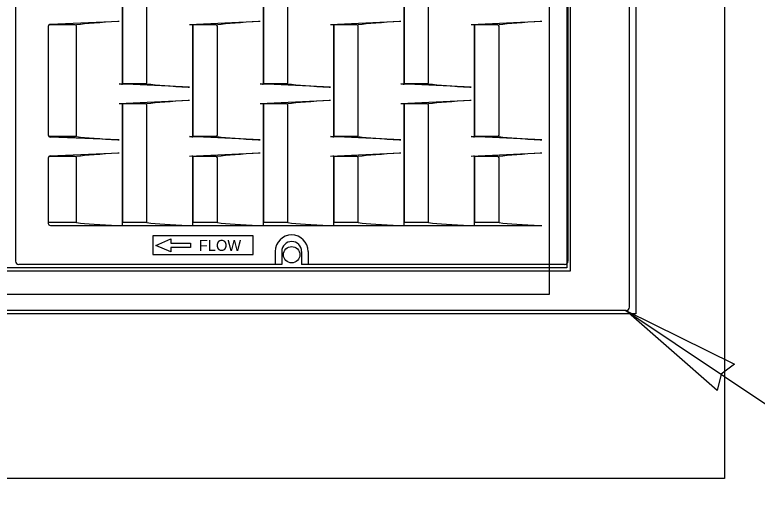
# Model space of a CAD drawing. Extents: x 99862 to 103151, y 100000 to 102076.
# Drawn here: x 101385.1 to 101526.3, y 101533.5 to 101624.9 of the extents above; entities that cross this region are included whole.
import ezdxf

# ---------------------------------------------------------------- set-up
doc = ezdxf.new("R2010")
doc.units = 0
for name, color, linetype in [('Level 1', 7, 'Continuous'), ('Level 10', 7, 'Continuous'), ('Level 11', 7, 'Continuous'), ('Level 15', 7, 'Continuous'), ('Level 2', 7, 'Continuous'), ('Level 20', 7, 'Continuous'), ('Level 5', 7, 'Continuous'), ('Level 7', 7, 'Continuous')]:
    doc.layers.add(name, color=color, linetype=linetype)

msp = doc.modelspace()

# ---------------------------------------------------------------- linework, layer by layer
at = {"layer": 'Level 1'}
for points in [[(101490.72, 101576.22), (101279.47, 101576.22), (101279.47, 101682.47), (101490.72, 101682.47)], [(101490.1, 101576.85), (101280.1, 101576.85), (101280.1, 101681.85), (101490.1, 101681.85)]]:
    msp.add_lwpolyline(points, close=True, dxfattribs=at)
msp.add_circle((101437.75, 101579.35), 1.56, dxfattribs=at)
at = {"layer": 'Level 10'}
for p, q in [((101486.78, 101571.85), (101486.78, 101686.85)), ((101284.28, 101571.85), (101486.78, 101571.85))]:
    msp.add_line(p, q, dxfattribs=at)
for points in [[(101405.57, 101633.06), (101405.57, 101611.8), (101409.97, 101611.8)], [(101410.23, 101612.06), (101410.23, 101632.8)], [(101432.36, 101633.06), (101432.36, 101611.8), (101436.75, 101611.8)], [(101437.02, 101612.06), (101437.02, 101632.8)], [(101459.14, 101633.06), (101459.14, 101611.8), (101463.54, 101611.8)], [(101463.8, 101612.06), (101463.8, 101632.8)], [(101391.46, 101622.74), (101391.46, 101602.11)], [(101396.58, 101623.06), (101391.63, 101623.06)], [(101396.84, 101602.05), (101396.84, 101622.8)], [(101418.97, 101623.06), (101418.97, 101601.79), (101423.36, 101601.79)], [(101423.36, 101623.06), (101418.97, 101623.06)], [(101423.62, 101602.05), (101423.62, 101622.8)], [(101445.75, 101623.06), (101445.75, 101601.79), (101450.15, 101601.79)], [(101450.15, 101623.06), (101445.75, 101623.06)], [(101450.41, 101602.05), (101450.41, 101622.8)], [(101472.54, 101623.06), (101472.54, 101601.79), (101476.93, 101601.79)], [(101476.93, 101623.06), (101472.54, 101623.06)], [(101477.19, 101602.05), (101477.19, 101622.8)], [(101405.57, 101608.05), (101405.57, 101585.53), (101410.23, 101585.53), (101410.23, 101607.79)], [(101409.97, 101608.05), (101405.57, 101608.05)], [(101432.36, 101608.05), (101432.36, 101585.53), (101437.02, 101585.53), (101437.02, 101607.79)], [(101436.75, 101608.05), (101432.36, 101608.05)], [(101459.14, 101608.05), (101459.14, 101585.53), (101463.8, 101585.53), (101463.8, 101607.79)], [(101463.54, 101608.05), (101459.14, 101608.05)], [(101391.63, 101601.79), (101396.58, 101601.79)], [(101391.46, 101597.72), (101391.46, 101585.53), (101396.84, 101585.53), (101396.84, 101587.17), (101396.84, 101597.78)], [(101396.58, 101598.04), (101391.63, 101598.04)], [(101418.97, 101598.04), (101418.97, 101585.53), (101423.62, 101585.53), (101423.62, 101597.78)], [(101423.36, 101598.04), (101418.97, 101598.04)], [(101445.75, 101598.04), (101445.75, 101585.53), (101450.41, 101585.53), (101450.41, 101597.78)], [(101450.15, 101598.04), (101445.75, 101598.04)], [(101472.54, 101598.04), (101472.54, 101585.53), (101477.19, 101585.53), (101477.19, 101597.78)], [(101476.93, 101598.04), (101472.54, 101598.04)]]:
    msp.add_lwpolyline(points, dxfattribs=at)
for centre, radius, start, end in [((101391.85, 101622.74), 0.391, 125.8762, 180), ((101396.58, 101622.8), 0.261, 360, 90), ((101423.36, 101622.8), 0.261, 360, 90), ((101450.15, 101622.8), 0.261, 360, 90), ((101476.93, 101622.8), 0.261, 360, 90), ((101409.97, 101612.06), 0.261, 270, 0), ((101436.75, 101612.06), 0.261, 270, 0), ((101463.54, 101612.06), 0.261, 270, 0), ((101409.97, 101607.79), 0.261, 360, 90), ((101436.75, 101607.79), 0.261, 360, 90), ((101463.54, 101607.79), 0.261, 360, 90), ((101391.85, 101602.11), 0.391, 180, 234.1238), ((101396.58, 101602.05), 0.261, 270, 0), ((101423.36, 101602.05), 0.261, 270, 0), ((101450.15, 101602.05), 0.261, 270, 0), ((101476.93, 101602.05), 0.261, 270, 0), ((101391.85, 101597.72), 0.391, 125.8762, 180), ((101396.58, 101597.78), 0.261, 0, 90), ((101423.36, 101597.78), 0.261, 360, 90), ((101450.15, 101597.78), 0.261, 360, 90), ((101476.93, 101597.78), 0.261, 360, 90)]:
    msp.add_arc(centre, radius, start, end, dxfattribs=at)
at = {"layer": 'Level 11'}
for p, q in [((101434.63, 101579.98), (101434.63, 101577.47)), ((101435.88, 101579.98), (101435.88, 101577.47)), ((101439.63, 101579.98), (101439.63, 101577.47)), ((101440.88, 101579.98), (101440.88, 101577.47))]:
    msp.add_line(p, q, dxfattribs=at)
msp.add_lwpolyline([(101411.35, 101582.96), (101411.35, 101579.41), (101430.4, 101579.41), (101430.4, 101582.96)], close=True, dxfattribs=at)
msp.add_lwpolyline([(101414.79, 101582.36), (101414.79, 101581.54), (101418.49, 101581.54), (101418.49, 101580.72), (101414.79, 101580.72), (101414.79, 101579.9), (101411.92, 101581.13), (101414.79, 101582.36)], dxfattribs=at)
for radius in [3.13, 1.88]:
    msp.add_arc((101437.75, 101579.98), radius, 360, 180, dxfattribs=at)
at = {"layer": 'Level 15'}
msp.add_lwpolyline([(101501.32, 101568.72), (101716.9, 101424.66), (101732.9, 101424.66)], dxfattribs=at)
msp.add_lwpolyline([(101501.32, 101568.72), (101521.96, 101558.53), (101519.43, 101556.63), (101518.65, 101553.56)], close=True, dxfattribs=at)
at = {"layer": 'Level 2'}
for p, q in [((101405.57, 101611.79), (101405.57, 101633.07)), ((101410.23, 101612.06), (101410.23, 101632.8)), ((101432.36, 101611.79), (101432.36, 101633.07)), ((101437.02, 101612.06), (101437.02, 101632.8)), ((101459.14, 101611.79), (101459.14, 101633.07)), ((101463.8, 101612.06), (101463.8, 101632.8)), ((101385.21, 101628.1), (101385.21, 101578.13)), ((101490.3, 101628.1), (101490.3, 101578.13)), ((101404.95, 101623.68), (101391.84, 101623.13)), ((101431.73, 101623.68), (101418.34, 101623.06)), ((101458.52, 101623.68), (101445.13, 101623.06)), ((101485.3, 101623.68), (101471.91, 101623.06)), ((101391.46, 101622.74), (101391.46, 101602.11)), ((101396.58, 101623.06), (101391.63, 101623.06)), ((101396.84, 101602.05), (101396.84, 101622.8)), ((101423.36, 101623.06), (101418.97, 101623.06)), ((101418.97, 101601.79), (101418.97, 101623.06)), ((101423.62, 101602.05), (101423.62, 101622.8)), ((101450.15, 101623.06), (101445.75, 101623.06)), ((101445.75, 101601.79), (101445.75, 101623.06)), ((101450.41, 101602.05), (101450.41, 101622.8)), ((101476.93, 101623.06), (101472.54, 101623.06)), ((101472.54, 101601.79), (101472.54, 101623.06)), ((101477.19, 101602.05), (101477.19, 101622.8)), ((101418.34, 101611.17), (101404.95, 101611.8)), ((101409.97, 101611.8), (101405.57, 101611.8)), ((101445.13, 101611.17), (101431.73, 101611.8)), ((101436.75, 101611.8), (101432.36, 101611.8)), ((101471.91, 101611.17), (101458.52, 101611.8)), ((101463.54, 101611.8), (101459.14, 101611.8)), ((101418.34, 101608.67), (101404.95, 101608.05)), ((101405.57, 101584.95), (101405.57, 101608.05)), ((101409.97, 101608.05), (101405.57, 101608.05)), ((101445.13, 101608.67), (101431.73, 101608.05)), ((101432.36, 101584.95), (101432.36, 101608.05)), ((101436.75, 101608.05), (101432.36, 101608.05)), ((101471.91, 101608.67), (101458.52, 101608.05)), ((101459.14, 101584.95), (101459.14, 101608.05)), ((101463.54, 101608.05), (101459.14, 101608.05)), ((101410.23, 101585.53), (101410.23, 101607.79)), ((101437.02, 101585.53), (101437.02, 101607.79)), ((101463.8, 101585.53), (101463.8, 101607.79)), ((101396.58, 101601.79), (101391.63, 101601.79)), ((101404.95, 101601.17), (101391.84, 101601.72)), ((101431.73, 101601.17), (101418.34, 101601.79)), ((101423.36, 101601.79), (101418.97, 101601.79)), ((101458.52, 101601.17), (101445.13, 101601.79)), ((101450.15, 101601.79), (101445.75, 101601.79)), ((101485.3, 101601.17), (101471.91, 101601.79)), ((101476.93, 101601.79), (101472.54, 101601.79)), ((101404.95, 101598.66), (101391.84, 101598.11)), ((101431.73, 101598.66), (101418.34, 101598.04)), ((101458.52, 101598.66), (101445.13, 101598.04)), ((101485.3, 101598.66), (101471.91, 101598.04)), ((101391.46, 101597.72), (101391.46, 101585.3)), ((101396.58, 101598.04), (101391.63, 101598.04)), ((101396.84, 101587.17), (101396.84, 101597.78)), ((101418.97, 101584.95), (101418.97, 101598.04)), ((101423.36, 101598.04), (101418.97, 101598.04)), ((101423.62, 101585.53), (101423.62, 101597.78)), ((101445.75, 101584.95), (101445.75, 101598.04)), ((101450.15, 101598.04), (101445.75, 101598.04)), ((101450.41, 101585.53), (101450.41, 101597.78)), ((101472.54, 101584.95), (101472.54, 101598.04)), ((101476.93, 101598.04), (101472.54, 101598.04)), ((101477.19, 101585.53), (101477.19, 101597.78)), ((101396.84, 101585.53), (101396.84, 101587.17)), ((101391.46, 101585.53), (101396.84, 101585.53)), ((101396.84, 101585.46), (101396.84, 101585.53)), ((101405.57, 101585.53), (101410.23, 101585.53)), ((101410.23, 101585.46), (101410.23, 101585.53)), ((101418.97, 101585.53), (101423.62, 101585.53)), ((101423.62, 101585.46), (101423.62, 101585.53)), ((101432.36, 101585.53), (101437.02, 101585.53)), ((101437.02, 101585.46), (101437.02, 101585.53)), ((101445.75, 101585.53), (101450.41, 101585.53)), ((101450.41, 101585.46), (101450.41, 101585.53)), ((101459.14, 101585.53), (101463.8, 101585.53)), ((101463.8, 101585.46), (101463.8, 101585.53)), ((101472.54, 101585.53), (101477.19, 101585.53)), ((101477.19, 101585.46), (101477.19, 101585.53)), ((101391.85, 101584.9), (101485.29, 101584.9)), ((101435.88, 101577.47), (101385.86, 101577.47)), ((101489.65, 101577.47), (101439.63, 101577.47))]:
    msp.add_line(p, q, dxfattribs=at)
for points in [[(101501.97, 101689.32), (101501.97, 101569.37)], [(101501.32, 101568.72), (101268.87, 101568.72)]]:
    msp.add_lwpolyline(points, dxfattribs=at)
for centre, radius, start, end in [((101391.85, 101622.74), 0.391, 92.6026, 180), ((101396.58, 101622.8), 0.261, 0, 90), ((101423.36, 101622.8), 0.261, 0, 90), ((101450.15, 101622.8), 0.261, 0, 90), ((101476.93, 101622.8), 0.261, 0, 90), ((101409.97, 101612.06), 0.261, 270, 0), ((101436.75, 101612.06), 0.261, 270, 0), ((101463.54, 101612.06), 0.261, 270, 0), ((101409.97, 101607.79), 0.261, 0, 90), ((101436.75, 101607.79), 0.261, 0, 90), ((101463.54, 101607.79), 0.261, 0, 90), ((101391.85, 101602.11), 0.391, 180, 267.3974), ((101396.58, 101602.05), 0.261, 270, 0), ((101423.36, 101602.05), 0.261, 270, 0), ((101450.15, 101602.05), 0.261, 270, 0), ((101476.93, 101602.05), 0.261, 270, 0), ((101391.85, 101597.72), 0.391, 92.6026, 180), ((101396.58, 101597.78), 0.261, 0, 90), ((101423.36, 101597.78), 0.261, 0, 90), ((101450.15, 101597.78), 0.261, 0, 90), ((101476.93, 101597.78), 0.261, 0, 90), ((101391.85, 101585.3), 0.391, 180, 270), ((101385.86, 101578.13), 0.652, 180, 270), ((101489.65, 101578.13), 0.652, 270, 0), ((101501.32, 101569.37), 0.652, 270, 0)]:
    msp.add_arc(centre, radius, start, end, dxfattribs=at)
for centre, major_axis, ratio, start_param, end_param in [((101411.97, 101623.43), (17.51, 0.8), 0.035758, 1.997966, 2.612379), ((101404.95, 101623.66), (0.625, 0.028), 0.035758, 1.569169, 1.997966), ((101438.75, 101623.43), (17.51, 0.8), 0.035758, 1.997966, 2.612379), ((101431.73, 101623.66), (0.625, 0.028), 0.035758, 1.569169, 1.997966), ((101465.54, 101623.43), (17.51, 0.8), 0.035758, 1.997966, 2.612379), ((101458.52, 101623.66), (0.625, 0.028), 0.035758, 1.569169, 1.997966), ((101492.33, 101623.43), (17.51, 0.8), 0.035758, 1.997966, 2.612379), ((101485.3, 101623.66), (0.625, 0.028), 0.035758, 1.569169, 1.997966), ((101418.34, 101623.03), (0.625, 0.028), 0.035758, 6.281558, 7.852354), ((101445.13, 101623.03), (0.625, 0.028), 0.035758, 6.281558, 7.852354), ((101471.91, 101623.03), (0.625, 0.028), 0.035758, 6.281558, 7.852354), ((101404.95, 101611.82), (-0.625, 0.028), 0.035758, 1.572424, 3.14322), ((101425.36, 101611.43), (-17.51, 0.8), 0.035758, 0.529214, 1.143627), ((101418.34, 101611.2), (-0.625, 0.028), 0.035758, 1.143627, 1.572424), ((101431.73, 101611.82), (-0.625, 0.028), 0.035758, 1.572424, 3.14322), ((101452.15, 101611.43), (-17.51, 0.8), 0.035758, 0.529214, 1.143627), ((101445.13, 101611.2), (-0.625, 0.028), 0.035758, 1.143627, 1.572424), ((101458.52, 101611.82), (-0.625, 0.028), 0.035758, 1.572424, 3.14322), ((101478.93, 101611.43), (-17.51, 0.8), 0.035758, 0.529214, 1.143627), ((101471.91, 101611.2), (-0.625, 0.028), 0.035758, 1.143627, 1.572424), ((101404.95, 101608.02), (0.625, 0.028), 0.035758, 6.281558, 7.852354), ((101425.36, 101608.42), (17.51, 0.8), 0.035758, 1.997966, 2.612379), ((101418.34, 101608.65), (0.625, 0.028), 0.035758, 1.569169, 1.997966), ((101431.73, 101608.02), (0.625, 0.028), 0.035758, 6.281558, 7.852354), ((101452.15, 101608.42), (17.51, 0.8), 0.035758, 1.997966, 2.612379), ((101445.13, 101608.65), (0.625, 0.028), 0.035758, 1.569169, 1.997966), ((101458.52, 101608.02), (0.625, 0.028), 0.035758, 6.281558, 7.852354), ((101478.93, 101608.42), (17.51, 0.8), 0.035758, 1.997966, 2.612379), ((101471.91, 101608.65), (0.625, 0.028), 0.035758, 1.569169, 1.997966), ((101411.97, 101601.42), (-17.51, 0.8), 0.035758, 0.529214, 1.143627), ((101404.95, 101601.19), (-0.625, 0.028), 0.035758, 1.143627, 1.572424), ((101418.34, 101601.81), (-0.625, 0.028), 0.035758, 1.572424, 3.14322), ((101438.75, 101601.42), (-17.51, 0.8), 0.035758, 0.529214, 1.143627), ((101431.73, 101601.19), (-0.625, 0.028), 0.035758, 1.143627, 1.572424), ((101445.13, 101601.81), (-0.625, 0.028), 0.035758, 1.572424, 3.14322), ((101465.54, 101601.42), (-17.51, 0.8), 0.035758, 0.529214, 1.143627), ((101458.52, 101601.19), (-0.625, 0.028), 0.035758, 1.143627, 1.572424), ((101471.91, 101601.81), (-0.625, 0.028), 0.035758, 1.572424, 3.14322), ((101492.33, 101601.42), (-17.51, 0.8), 0.035758, 0.529214, 1.143627), ((101485.3, 101601.19), (-0.625, 0.028), 0.035758, 1.143627, 1.572424), ((101411.97, 101598.41), (17.51, 0.8), 0.035758, 1.997966, 2.612379), ((101404.95, 101598.64), (0.625, 0.028), 0.035758, 1.569169, 1.997966), ((101438.75, 101598.41), (17.51, 0.8), 0.035758, 1.997966, 2.612379), ((101431.73, 101598.64), (0.625, 0.028), 0.035758, 1.569169, 1.997966), ((101465.54, 101598.41), (17.51, 0.8), 0.035758, 1.997966, 2.612379), ((101458.52, 101598.64), (0.625, 0.028), 0.035758, 1.569169, 1.997966), ((101492.33, 101598.41), (17.51, 0.8), 0.035758, 1.997966, 2.612379), ((101485.3, 101598.64), (0.625, 0.028), 0.035758, 1.569169, 1.997966), ((101418.34, 101598.02), (0.625, 0.028), 0.035758, 6.281558, 7.852354), ((101445.13, 101598.02), (0.625, 0.028), 0.035758, 6.281558, 7.852354), ((101471.91, 101598.02), (0.625, 0.028), 0.035758, 6.281558, 7.852354), ((101411.97, 101586.13), (-17.51, 0), 0.076923, 0.527586, 1.142), ((101425.36, 101586.13), (-17.51, 0), 0.076923, 0.527586, 1.142), ((101438.75, 101586.13), (-17.51, 0), 0.076923, 0.527586, 1.142), ((101452.15, 101586.13), (-17.51, 0), 0.076923, 0.527586, 1.142), ((101465.54, 101586.13), (-17.51, 0), 0.076923, 0.527586, 1.142), ((101478.93, 101586.13), (-17.51, 0), 0.076923, 0.527586, 1.142), ((101492.33, 101586.13), (-17.51, 0), 0.076923, 0.527586, 1.142), ((101404.95, 101584.95), (-0.625, 0), 0.076923, 1.142, 1.570796), ((101404.95, 101584.95), (-0.625, 0), 0.076923, 1.570796, 3.141593), ((101418.34, 101584.95), (-0.625, 0), 0.076923, 1.142, 1.570796), ((101418.34, 101584.95), (-0.625, 0), 0.076923, 1.570796, 3.141593), ((101431.73, 101584.95), (-0.625, 0), 0.076923, 1.142, 1.570796), ((101431.73, 101584.95), (-0.625, 0), 0.076923, 1.570796, 3.141593), ((101445.13, 101584.95), (-0.625, 0), 0.076923, 1.142, 1.570796), ((101445.13, 101584.95), (-0.625, 0), 0.076923, 1.570796, 3.141593), ((101458.52, 101584.95), (-0.625, 0), 0.076923, 1.142, 1.570796), ((101458.52, 101584.95), (-0.625, 0), 0.076923, 1.570796, 3.141593), ((101471.91, 101584.95), (-0.625, 0), 0.076923, 1.142, 1.570796), ((101471.91, 101584.95), (-0.625, 0), 0.076923, 1.570796, 3.141593), ((101485.29, 101584.95), (-0.625, 0), 0.076923, 1.142, 1.570796), ((101485.3, 101584.95), (-0.625, 0), 0.076923, 1.142, 1.570796)]:
    msp.add_ellipse(centre, major_axis=major_axis, ratio=ratio, start_param=start_param, end_param=end_param, dxfattribs=at)
at = {"layer": 'Level 5'}
for radius in [280, 260, 240]:
    msp.add_circle((101385.1, 101629.35), radius, dxfattribs=at)
at = {"layer": 'Level 7'}
for p, q in [((101520.1, 101721.85), (101520.1, 101536.85)), ((101503.22, 101690.6), (101503.22, 101568.1)), ((101503.22, 101568.1), (101266.97, 101568.1)), ((101520.1, 101536.85), (101250.1, 101536.85))]:
    msp.add_line(p, q, dxfattribs=at)

# ---------------------------------------------------------------- texts
at = {"layer": 'Level 20'}
msp.add_text('FLOW', height=2.087, dxfattribs=at).set_placement((101420.09, 101580.08))

doc.saveas('drawing.dxf')
